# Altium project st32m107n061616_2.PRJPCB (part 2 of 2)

## Sheet WIFIZGMD.SchDoc
size 297 x 210 mm
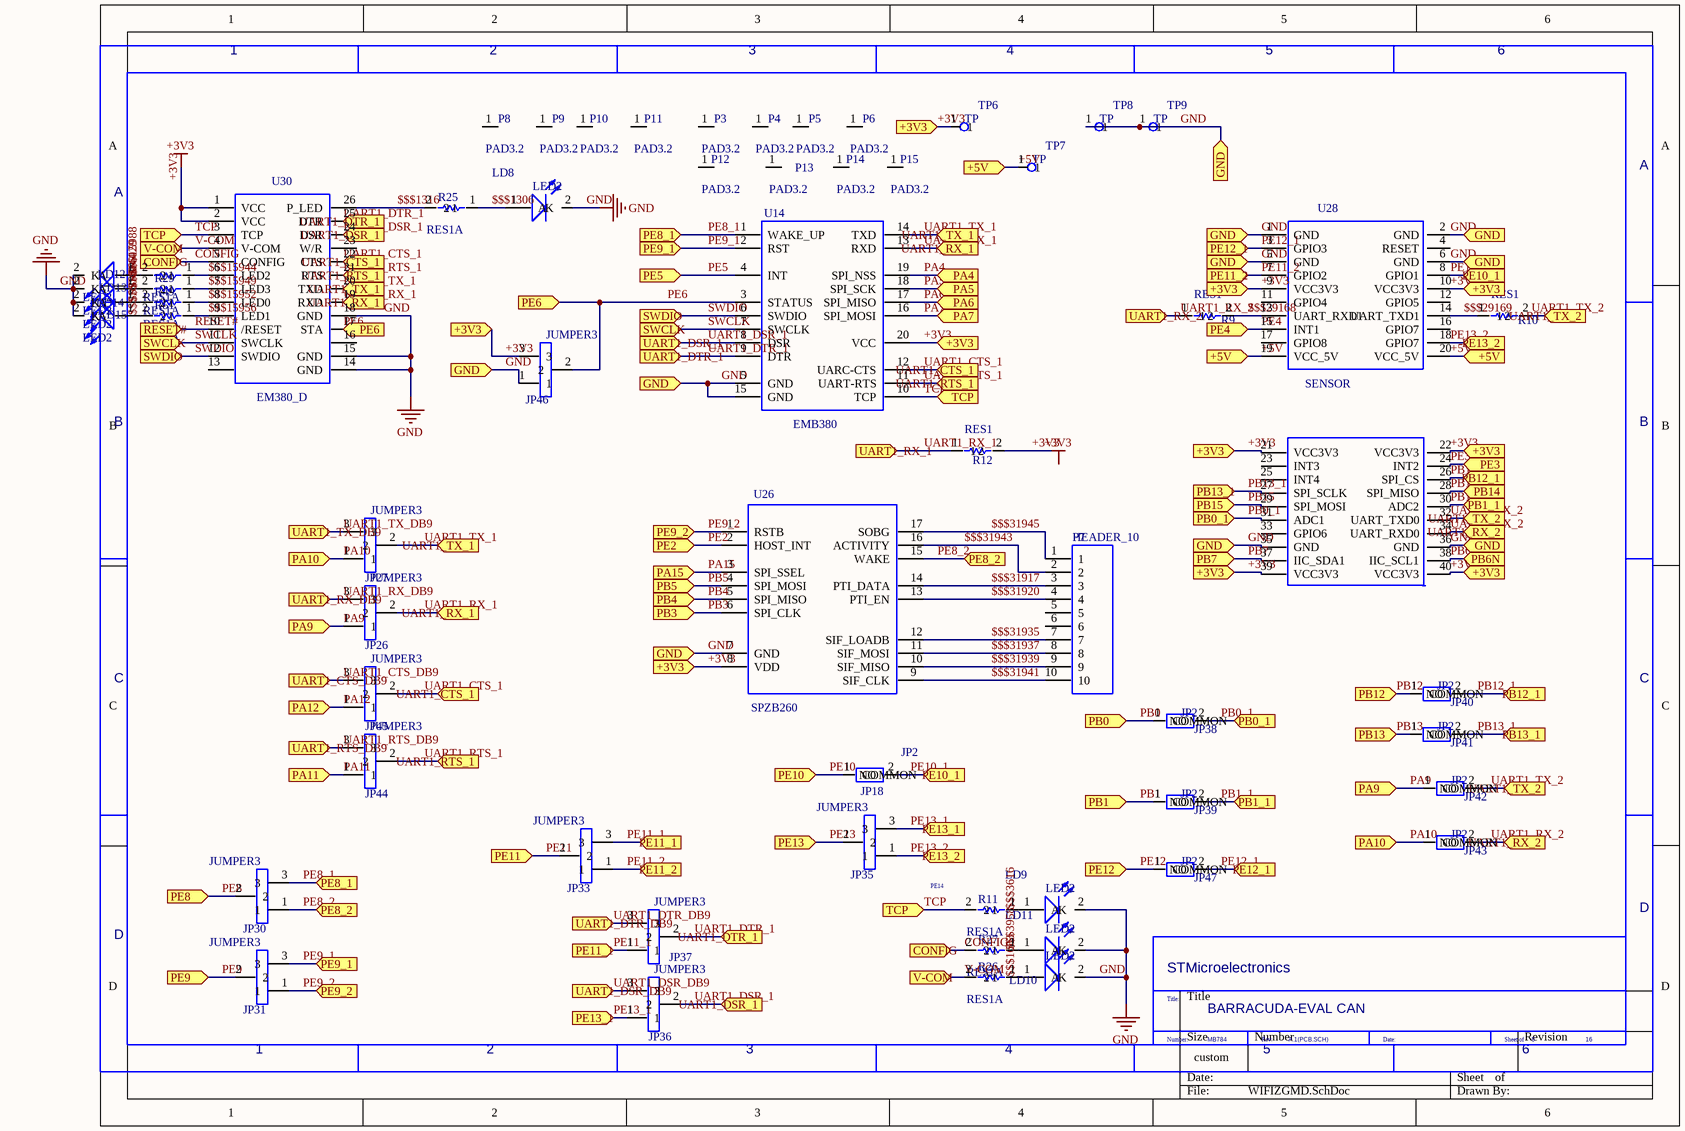
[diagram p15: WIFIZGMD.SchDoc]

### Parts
JP18  JP2
JP26  JUMPER3
JP27  JUMPER3
JP30  JUMPER3
JP31  JUMPER3
JP33  JUMPER3
JP35  JUMPER3
JP36  JUMPER3
JP37  JUMPER3
JP38  JP2
JP39  JP2
JP40  JP2
JP41  JP2
JP42  JP2
JP43  JP2
JP44  JUMPER3
JP45  JUMPER3
JP46  JUMPER3
JP47  JP2
LD8  LED2
LD9  LED2
LD10  LED2
LD11  LED2
LD12  LED2
LD13  LED2
LD14  LED2
LD15  LED2
P3  PAD3.2
P4  PAD3.2
P5  PAD3.2
P6  PAD3.2
P7  HEADER_10
P8  PAD3.2
P9  PAD3.2
P10  PAD3.2
P11  PAD3.2
P12  PAD3.2
P13  PAD3.2
P14  PAD3.2
P15  PAD3.2
R9  RES1
R10  RES1
R11  RES1A
R12  RES1
R25  RES1A
R26  RES1A
R27  RES1A
R28  RES1A
R29  RES1A
R49  RES1A
R51  RES1A
TP6  TP
TP7  TP
TP8  TP
TP9  TP
U14  EMB380
U26  SPZB260
U28  SENSOR
U30  EM380_D

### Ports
+3V3, +5V, CONFIG, GND, PA4, PA5, PA6, PA7, PA9, PA10, PA11, PA12, PA15, PB0, PB0_1, PB1, PB1_1, PB3, PB4, PB5, PB6N, PB7, PB12, PB12_1, PB13, PB13_1, PB14, PB15, PE2, PE3, PE4, PE5, PE6, PE8, PE8_1, PE8_2, PE9, PE9_1, PE9_2, PE10, PE10_1, PE11, PE11_1, PE11_2, PE12, PE12_1, PE13, PE13_1, PE13_2, RESET#, SWCLK, SWDIO, TCP, UART1_CTS_1, UART1_CTS_DB9, UART1_DSR_1, UART1_DSR_DB9, UART1_DTR_1, UART1_DTR_DB9, UART1_RTS_1, UART1_RTS_DB9, UART1_RX_1, UART1_RX_2, UART1_RX_DB9, UART1_TX_1, UART1_TX_2, UART1_TX_DB9, V-COM

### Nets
+3V3: JP46.3 R12.2 TP6.1 U14.20(VCC) U26.8(VDD) U28.9(VCC3V3) U28.10(VCC3V3) U28.21(VCC3V3) U28.22(VCC3V3) U28.39(VCC3V3) U28.40(VCC3V3) U30.1(VCC) U30.2(VCC) ; port +3V3
GND: JP45.1 JP46.1 LD8.2(K) LD9.2(K) LD10.2(K) LD11.2(K) LD12.2(K) LD13.2(K) LD14.2(K) LD15.2(K) TP8.1 TP9.1 U14.5(GND) U14.15(GND) U26.7(GND) U28.1(GND) U28.2(GND) U28.5(GND) U28.6(GND) U28.35(GND) U28.36(GND) U30.14(GND) U30.15(GND) U30.18(GND) ; port GND, port PA12  [also labelled PA12]  [project net $$$275]
$$$1306: LD8.1(A) R25.1
$$$1316: R25.2 U30.26(P_LED)
$$$1683: LD10.1(A) R26.1
$$$3616: LD9.1(A) R11.1
$$$3958: LD11.1(A) R27.1
$$$15944: R28.1 U30.6(LED2)
$$$15949: R29.1 U30.7(LED3)
$$$15952: R49.1 U30.8(LED0)
$$$15956: R51.1 U30.9(LED1)
$$$15988: LD12.1(A) R28.2
$$$16029: LD13.1(A) R29.2
$$$16044: LD14.1(A) R49.2
$$$16049: LD15.1(A) R51.2
$$$29168: R9.2 U28.13(UART_RXD1)
$$$29169: R10.1 U28.14(UART_TXD1)
$$$31917: P7.3 U26.14(PTI_DATA)
$$$31920: P7.4 U26.13(PTI_EN)
$$$31935: P7.7 U26.12(SIF_LOADB)
$$$31937: P7.8 U26.11(SIF_MOSI)
$$$31939: P7.9 U26.10(SIF_MISO)
$$$31941: P7.10 U26.9(SIF_CLK)
$$$31943: P7.2 U26.16(ACTIVITY)
$$$31945: P7.1 U26.17(SOBG)
+5V: TP7.1 U28.19(VCC_5V) U28.20(VCC_5V) ; port +5V
CONFIG: R27.2 U30.5(CONFIG) ; port CONFIG
PA4: U14.19(SPI_NSS) ; port PA4
PA5: U14.18(SPI_SCK) ; port PA5
PA6: U14.17(SPI_MISO) ; port PA6
PA7: U14.16(SPI_MOSI) ; port PA7
PA9: JP26.1 JP42.1(COMMON) ; port PA9
PA10: JP27.1 JP43.1(COMMON) ; port PA10
PA11: JP44.1 ; port PA11
PA15: U26.3(SPI_SSEL) ; port PA15
PB0: JP38.1(COMMON) ; port PB0
PB0_1: JP38.2(NO) U28.31(ADC1) ; port PB0_1
PB1: JP39.1(COMMON) ; port PB1
PB1_1: JP39.2(NO) U28.30(ADC2) ; port PB1_1
PB3: U26.6(SPI_CLK) ; port PB3
PB4: U26.5(SPI_MISO) ; port PB4
PB5: U26.4(SPI_MOSI) ; port PB5  [project net PB11]
PB6N: U28.38(IIC_SCL1) ; port PB6N
PB7: U28.37(IIC_SDA1) ; port PB7
PB12: JP40.1(COMMON) ; port PB12
PB12_1: JP40.2(NO) U28.26(SPI_CS) ; port PB12_1
PB13: JP41.1(COMMON) ; port PB13
PB13_1: JP41.2(NO) U28.27(SPI_SCLK) ; port PB13_1
PB14: U28.28(SPI_MISO) ; port PB14
PB15: U28.29(SPI_MOSI) ; port PB15
PE2: U26.2(HOST_INT) ; port PE2
PE3: U28.24(INT2) ; port PE3
PE4: U28.15(INT1) ; port PE4
PE5: U14.4(INT) ; port PE5
PE6: JP46.2 U14.3(STATUS) U30.17(STA) ; port PE6
PE8: JP30.2 ; port PE8
PE8_1: JP30.3 U14.1(WAKE_UP) ; port PE8_1
PE8_2: JP30.1 U26.15(WAKE) ; port PE8_2
PE9: JP31.2 ; port PE9
PE9_1: JP31.3 U14.2(RST) ; port PE9_1
PE9_2: JP31.1 U26.1(RSTB) ; port PE9_2
PE10: JP18.1(COMMON) ; port PE10
PE10_1: JP18.2(NO) U28.8(GPIO1) ; port PE10_1
PE11: JP33.2 ; port PE11
PE11_1: JP33.3 JP37.1 ; port PE11_1
PE11_2: JP33.1 U28.7(GPIO2) ; port PE11_2
PE12: JP47.1(COMMON) ; port PE12
PE12_1: JP47.2(NO) U28.3(GPIO3) ; port PE12_1
PE13: JP35.2 ; port PE13
PE13_1: JP35.3 JP36.1 ; port PE13_1
PE13_2: JP35.1 U28.18(GPIO7) ; port PE13_2
RESET#: U30.10(/RESET) ; port RESET#
SWCLK: U14.7(SWCLK) U30.11(SWCLK) ; port SWCLK
SWDIO: U14.6(SWDIO) U30.12(SWDIO) ; port SWDIO
TCP: R11.2 U14.10(TCP) U30.3(TCP) ; port TCP
UART1_CTS_1: JP45.2 U14.12(UARC-CTS) U30.22(CTS) ; port UART1_CTS_1
UART1_CTS_DB9: JP45.3 ; port UART1_CTS_DB9
UART1_DSR_1: JP36.2 U14.8(DSR) U30.24(DSR) ; port UART1_DSR_1
UART1_DSR_DB9: JP36.3 ; port UART1_DSR_DB9
UART1_DTR_1: JP37.2 U14.9(DTR) U30.25(DTR) ; port UART1_DTR_1
UART1_DTR_DB9: JP37.3 ; port UART1_DTR_DB9
UART1_RTS_1: JP44.2 U14.11(UART-RTS) U30.21(RTS) ; port UART1_RTS_1
UART1_RTS_DB9: JP44.3 ; port UART1_RTS_DB9
UART1_RX_1: JP26.2 R12.1 U14.13(RXD) U30.19(RXD) ; port UART1_RX_1
UART1_RX_2: JP43.2(NO) R9.1 U28.34(UART_RXD0) ; port UART1_RX_2
UART1_RX_DB9: JP26.3 ; port UART1_RX_DB9
UART1_TX_1: JP27.2 U14.14(TXD) U30.20(TXD) ; port UART1_TX_1
UART1_TX_2: JP42.2(NO) R10.2 U28.32(UART_TXD0) ; port UART1_TX_2
UART1_TX_DB9: JP27.3 ; port UART1_TX_DB9
V-COM: R26.2 U30.4(V-COM) ; port V-COM

Not connected (* = marked no-connect by the designer): P3 1; P4 1; P5 1; P6 1; P7 5 6; P8 1; P9 1; P10 1; P11 1; P12 1; P13 1; P14 1; P15 1; U28 4(RESET) 11(GPIO4) 12(GPIO5) 16(GPIO7) 17(GPIO8) 23(INT3) 25(INT4) 33(GPIO6); U30 13 16 23(W/R)

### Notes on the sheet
- 1
- 2
- 3
- 4
- 5
- 6
- A
- B
- C
- D
- PE14
- Title:
- STMicroelectronics
- BARRACUDA-EVAL CAN
- (near JP31) 1
- Number:
- MB784
- Rev:
- A.1(PCB.SCH)
- Date:
- Sheet of
- 8
- 16

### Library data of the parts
JP18 JP38-JP43 JP47 = JP2: PCB DECAL: SIP2
JP26 JP27 JP30 JP31 JP33 JP35-JP37 JP44-JP46 = JUMPER3: PCB DECAL: SIP3
LD8-LD15 = LED2: Typical RED, GREEN, YELLOW, AMBER GaAs LED; PCB DECAL: D0603
P7 = HEADER_10: Header, 10-Pin; Manufacturer: Generic Components; VALUE: Header 10; Class: Connector; PCB DECAL: HDR1X10
P13-P15 = PAD3.2: PCB DECAL: MARK_MY
R9 R10 R12 = RES1: Resistor; Value: 1K; PCB DECAL: AXIAL-0.3
R11 R25-R29 R49 R51 = RES1A: Resistor; Value: 1K; PCB DECAL: AXIAL-0.3
U14 = EMB380: PCB DECAL: EMB380A
U26 = SPZB260: PCB DECAL: SPZB260PCB
U28 = SENSOR: PCB DECAL: SENSORP

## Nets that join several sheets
$$$275: IOPERIPHERALS (42 pins), EXTENSIONCONNECTOR (13 pins), IO_EXPANDOR (7 pins), JTAG&TRACE (25 pins), LCD (CN14.22 CN14.26 CN14.27), MCU (14 pins), MICROSDCARD (CN16.6 CN16.9), MOTORCONTROL (27 pins), POWER (40 pins), SMARTCARD (13 pins), USART&IRDA (22 pins), USB_OTG_FS (8 pins), AUDIO (26 pins), CAN (10 pins), ETHERNET (21 pins), WIFIZGMD (24 pins)
+2V5: POWER (C51.1 TP5.1 U27.2), AUDIO (8 pins)
+3V3: IOPERIPHERALS (19 pins), EXTENSIONCONNECTOR (CN8.48), IO_EXPANDOR (10 pins), JTAG&TRACE (10 pins), LCD (CN14.24 CN14.25), MCU (5 pins), MICROSDCARD (CN16.4 R138.2), MOTORCONTROL (CN17.28 R146.2), POWER (14 pins), SMARTCARD (8 pins), USART&IRDA (12 pins), USB_OTG_FS (R33.2 R34.1 R40.1), AUDIO (C42.2 U13.33), CAN (6 pins), ETHERNET (27 pins), WIFIZGMD (13 pins)
+5V: LCD (CN14.23 CN14.28), MOTORCONTROL (CN17.25), POWER (10 pins), SMARTCARD (C21.1 C25.1 U10.6), USB_OTG_FS (U3.5), AUDIO (C37.1 C38.1 U13.5 U13.8)
D5V: EXTENSIONCONNECTOR (CN8.49 CN9.19), POWER (JP25.4)
$$$17347: EXTENSIONCONNECTOR (CN8.17), LCD (CN14.3), MCU (U9.78), MICROSDCARD (CN16.2 CN16.5 R136.1 R138.1)
ANTI_TAMPER: IOPERIPHERALS (R105.2), MCU (JP1.3)
BNC1: IOPERIPHERALS (CN10.5 CN11.5 SB3.1 SB4.1), EXTENSIONCONNECTOR (CN8.24), MCU (U9.83), MOTORCONTROL (7 pins)
BOOTLOADER_BOOT0: MCU (D1.2), USART&IRDA (U11.16)
BOOTLOADER_RESET: MCU (D2.2), USART&IRDA (U11.19)
EXP_IO1: IOPERIPHERALS (R98.2), IO_EXPANDOR (U8.1)
EXP_IO2: IOPERIPHERALS (R99.2), IO_EXPANDOR (U8.16)
EXP_IO3: IOPERIPHERALS (R100.2), IO_EXPANDOR (U8.15)
EXP_IO4: IOPERIPHERALS (R101.2), IO_EXPANDOR (U8.13)
EXP_IO5: IOPERIPHERALS (R102.2), IO_EXPANDOR (U8.12)
EXP_IO6: IO_EXPANDOR (U8.11), AUDIO (R82.2)
EXP_IO7: IO_EXPANDOR (R58.1 U8.8 U8.9), ETHERNET (R41.1)
EXP_IO9: IOPERIPHERALS (U16.9), IO_EXPANDOR (U7.12)
EXP_IO10: IOPERIPHERALS (U16.8), IO_EXPANDOR (U7.11)
EXP_IO11: IO_EXPANDOR (R57.1 U7.8 U7.9), POWER (R163.1)
ICC_CNT_EN: MCU (JP1.1), POWER (R152.2 U24.12)
MC_ENINDEX: MCU (JP10.1), MOTORCONTROL (C67.2 CN17.34)
MC_HEATSINKTEMPERATURE: MCU (R165.2), MOTORCONTROL (R85.2)
MICROSDCARD_CS: MCU (JP15.2), MICROSDCARD (R136.2)
MII_COL: MCU (JP10.3), ETHERNET (RS2.4)
MII_CRS: MCU (JP14.1), ETHERNET (RS2.8)
MII_RX_DV/RMII_CRSDV: MCU (JP13.3), ETHERNET (JP2.1 RS4.6)
MII_RXD0: MCU (JP12.3), ETHERNET (RS4.4)
MII_RXD1: MCU (JP11.3), ETHERNET (RS4.2)
PA0: EXTENSIONCONNECTOR (CN8.9), MCU (JP14.2 U9.23), MOTORCONTROL (CN17.23), POWER (T1.1 T1.2 T1.5 T1.6)
PA1: EXTENSIONCONNECTOR (CN9.44), MCU (U9.24), ETHERNET (JP3.2)
PA2: EXTENSIONCONNECTOR (CN9.43), MCU (U9.25), ETHERNET (R162.1)
PA4: EXTENSIONCONNECTOR (CN9.41), MCU (JP15.1 U9.29), AUDIO (R83.2), WIFIZGMD (U14.19)
PA5: EXTENSIONCONNECTOR (CN9.40), MCU (U9.30), MOTORCONTROL (R84.2), WIFIZGMD (U14.18)
PA6: EXTENSIONCONNECTOR (CN9.38), MCU (U9.31), POWER (JP19.2), WIFIZGMD (U14.17)
PA7: EXTENSIONCONNECTOR (CN9.37), MCU (U9.32), MOTORCONTROL (R169.1), WIFIZGMD (U14.16)
PA8: EXTENSIONCONNECTOR (CN8.6), MCU (U9.67), ETHERNET (JP4.3)
PA9: EXTENSIONCONNECTOR (CN8.7), WIFIZGMD (JP26.1 JP42.1)
PA10: EXTENSIONCONNECTOR (CN8.8), MCU (U9.69), USB_OTG_FS (R38.2), WIFIZGMD (JP27.1 JP43.1)
PA11: EXTENSIONCONNECTOR (CN8.12), MCU (U9.70), USB_OTG_FS (R42.2 U4.3), WIFIZGMD (JP44.1)
PA14: EXTENSIONCONNECTOR (CN8.16), JTAG&TRACE (CN13.9 R125.2), MCU (U9.76)
PA15: EXTENSIONCONNECTOR (CN8.20), JTAG&TRACE (CN13.5 R123.1), MCU (U9.77), WIFIZGMD (U26.3)
PB0: EXTENSIONCONNECTOR (CN9.34), MCU (U9.35), MOTORCONTROL (R167.1), WIFIZGMD (JP38.1)
PB1: EXTENSIONCONNECTOR (CN9.33), MCU (U9.36), MOTORCONTROL (R168.1), WIFIZGMD (JP39.1)
PB2: EXTENSIONCONNECTOR (CN9.32), LCD (CN14.1), MCU (R60.1 U9.37)
PB3: EXTENSIONCONNECTOR (CN8.33), JTAG&TRACE (CN13.13 R122.1), MCU (U9.89), WIFIZGMD (U26.6)
PB4: EXTENSIONCONNECTOR (CN8.34), JTAG&TRACE (CN13.3 JP20.1 R124.1), MCU (U9.90), WIFIZGMD (U26.5)
PB6: EXTENSIONCONNECTOR (CN8.36), MCU (JP9.1 U9.92), CAN (U6.1)
PB6N: IOPERIPHERALS (U16.14 U17.6), IO_EXPANDOR (U7.4 U8.4), MCU (R3.2 R131.2), AUDIO (U13.2), WIFIZGMD (U28.38)
PB7: IOPERIPHERALS (U16.13 U17.5), EXTENSIONCONNECTOR (CN8.37), IO_EXPANDOR (U7.5 U8.5), MCU (R4.2 R5.2), AUDIO (U13.1), WIFIZGMD (U28.37)
PB8: EXTENSIONCONNECTOR (CN8.45), MCU (U9.95), ETHERNET (RS1.6)
PB10: EXTENSIONCONNECTOR (CN9.18), MCU (U9.47), ETHERNET (RS2.6)
PB11: IOPERIPHERALS (R104.2), EXTENSIONCONNECTOR (CN8.35 CN8.46 CN9.17), MCU (TP4.1 U9.48 U9.91 U9.96), CAN (R45.2), ETHERNET (RS3.6), WIFIZGMD (U26.4)
PB12: EXTENSIONCONNECTOR (CN9.16), MCU (U9.51), AUDIO (U13.40), ETHERNET (RS3.4), WIFIZGMD (JP40.1)
PB13: EXTENSIONCONNECTOR (CN9.15), MCU (U9.52), AUDIO (U13.38), ETHERNET (RS3.2), WIFIZGMD (JP41.1)
PB14: EXTENSIONCONNECTOR (CN9.14), IO_EXPANDOR (R159.1), MCU (U9.53), WIFIZGMD (U28.28)
PB15: EXTENSIONCONNECTOR (CN9.13), MCU (U9.54), AUDIO (R24.2 U13.39), WIFIZGMD (U28.29)
PC0: EXTENSIONCONNECTOR (CN9.48), MCU (R165.1 U9.15), SMARTCARD (U10.3)
PC1: EXTENSIONCONNECTOR (CN9.47), MCU (U9.16), ETHERNET (U1.31)
PC2: EXTENSIONCONNECTOR (CN9.46), MCU (U9.17), ETHERNET (RS1.4)
PC3: EXTENSIONCONNECTOR (CN9.45), MCU (U9.18), ETHERNET (RS1.2)
PC4: IOPERIPHERALS (R103.1), EXTENSIONCONNECTOR (CN9.36), MCU (U9.33)
PC5: EXTENSIONCONNECTOR (CN9.35), MCU (U9.34), POWER (R154.1)
PC6: EXTENSIONCONNECTOR (CN8.2), MCU (U9.63), AUDIO (U13.37)
PC7: EXTENSIONCONNECTOR (CN8.3), MCU (U9.64), MOTORCONTROL (C71.2 JP22.2)
PC8: EXTENSIONCONNECTOR (CN8.4), MCU (U9.65), MOTORCONTROL (C69.2 CN17.29)
PC9: EXTENSIONCONNECTOR (CN8.5), MCU (U9.66), USB_OTG_FS (R36.2)
PC11: EXTENSIONCONNECTOR (CN8.18), LCD (CN14.29), MCU (U9.79), MICROSDCARD (R135.1)
PC12: EXTENSIONCONNECTOR (CN8.21), LCD (CN14.30), MCU (U9.80), MICROSDCARD (CN16.3)
PD0: EXTENSIONCONNECTOR (CN8.22), MCU (U9.81), CAN (R44.2)
PD1: EXTENSIONCONNECTOR (CN8.23), MCU (U9.82), CAN (U5.1)
PD3: IOPERIPHERALS (R96.2), EXTENSIONCONNECTOR (CN8.25), MCU (U9.84)
PD4: IOPERIPHERALS (R97.2), EXTENSIONCONNECTOR (CN8.26), MCU (U9.85)
PD5: EXTENSIONCONNECTOR (CN8.27), MCU (U9.86), USART&IRDA (U11.13 U12.3)
PD6: EXTENSIONCONNECTOR (CN8.28), MCU (U9.87), USART&IRDA (JP16.2)
PD7: IOPERIPHERALS (R94.2), EXTENSIONCONNECTOR (CN8.29), MCU (U9.88)
PD11: EXTENSIONCONNECTOR (CN9.6), MCU (U9.58), ETHERNET (RS1.8)
PD12: EXTENSIONCONNECTOR (CN9.5), MCU (U9.59), ETHERNET (RS2.2)
PD13: IOPERIPHERALS (R95.2), EXTENSIONCONNECTOR (CN9.4), MCU (U9.60)
PD14: EXTENSIONCONNECTOR (CN9.3), MCU (U9.61), MOTORCONTROL (C68.2 CN17.31 JP21.1)
PD15: EXTENSIONCONNECTOR (CN9.2), MCU (U9.62), MOTORCONTROL (C70.2 CN17.33)
PE0: EXTENSIONCONNECTOR (CN8.38), MCU (U9.97), MICROSDCARD (JP48.1), MOTORCONTROL (CN17.21)
PE1: EXTENSIONCONNECTOR (CN8.40), MCU (U9.98), USB_OTG_FS (R35.1)
PE2: EXTENSIONCONNECTOR (CN8.41), MCU (U9.1), WIFIZGMD (U26.2)
PE3: EXTENSIONCONNECTOR (CN8.42), MCU (U9.2), WIFIZGMD (U28.24)
PE4: EXTENSIONCONNECTOR (CN8.43), MCU (U9.3), WIFIZGMD (U28.15)
PE5: EXTENSIONCONNECTOR (CN8.44), MCU (U9.4), WIFIZGMD (U14.4)
PE6: EXTENSIONCONNECTOR (CN8.47), MCU (U9.5), WIFIZGMD (JP46.2 U14.3 U30.17)
PE7: EXTENSIONCONNECTOR (CN9.31), MCU (U9.38), SMARTCARD (R69.1)
PE8: EXTENSIONCONNECTOR (CN9.29), MCU (U9.39), MOTORCONTROL (CN17.5), WIFIZGMD (JP30.2)
PE9: EXTENSIONCONNECTOR (CN9.28), MCU (U9.40), MOTORCONTROL (CN17.3), WIFIZGMD (JP31.2)
PE10: EXTENSIONCONNECTOR (CN9.27), MCU (U9.41), MOTORCONTROL (CN17.9), WIFIZGMD (JP18.1)
PE11: EXTENSIONCONNECTOR (CN9.26), MCU (U9.42), MOTORCONTROL (CN17.7), WIFIZGMD (JP33.2)
PE12: EXTENSIONCONNECTOR (CN9.25), MCU (U9.43), MOTORCONTROL (CN17.13), WIFIZGMD (JP47.1)
PE13: EXTENSIONCONNECTOR (CN9.22), MCU (U9.44), MOTORCONTROL (CN17.11), WIFIZGMD (JP35.2)
PE14: EXTENSIONCONNECTOR (CN9.21), MCU (U9.45), SMARTCARD (R166.1)
PE15: EXTENSIONCONNECTOR (CN9.20), MCU (U9.46), MOTORCONTROL (R139.2)
RESET#: EXTENSIONCONNECTOR (R88.2), JTAG&TRACE (CN7.15 CN13.15 JP20.2), LCD (CN14.5), MCU (6 pins), ETHERNET (U1.29), WIFIZGMD (U30.10)
SMARTCARD_CLK: MCU (JP11.1), SMARTCARD (U10.24)
SMARTCARD_IO: MCU (JP13.1), SMARTCARD (R68.2)
SMARTCARD_RST: MCU (JP12.1), SMARTCARD (U10.20)
SWCLK: JTAG&TRACE (CN7.9 R17.2), WIFIZGMD (U14.7 U30.11)
SWDIO: JTAG&TRACE (CN7.7 R16.1), WIFIZGMD (U14.6 U30.12)
TOUCHSCREEN_X+: IO_EXPANDOR (U7.13), LCD (CN14.32)
TOUCHSCREEN_X-: IO_EXPANDOR (U7.16), LCD (CN14.31)
TOUCHSCREEN_Y+: IO_EXPANDOR (U7.15), LCD (CN14.34)
TOUCHSCREEN_Y-: IO_EXPANDOR (U7.1), LCD (CN14.33)
UART1_CTS_DB9: USART&IRDA (U29.15), WIFIZGMD (JP45.3)
UART1_DSR_DB9: USART&IRDA (U29.13), WIFIZGMD (JP36.3)
UART1_DTR_DB9: USART&IRDA (U29.17), WIFIZGMD (JP37.3)
UART1_RTS_DB9: USART&IRDA (U29.12), WIFIZGMD (JP44.3)
UART1_RX_DB9: USART&IRDA (U29.18), WIFIZGMD (JP26.3)
UART1_TX_DB9: USART&IRDA (U29.14), WIFIZGMD (JP27.3)
USB_VBUS: MCU (JP32.1), POWER (JP25.2), USB_OTG_FS (5 pins)
WAKEUP: IOPERIPHERALS (R116.2), MCU (JP14.3)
